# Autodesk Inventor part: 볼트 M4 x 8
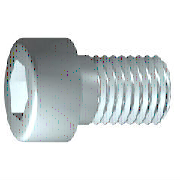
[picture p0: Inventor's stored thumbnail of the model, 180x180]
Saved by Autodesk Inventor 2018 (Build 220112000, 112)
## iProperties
IsCustomPart: 1
Created: 2012-02
Part Number: 볼트 M4 x 8
Material: 스테인리스강
Description: 6각 소켓 머리 캡 나사
Document SubType Name: Modeling
Standard: ISO 4762
Designer: mduedu
Standard Revision: Fourth edition 2004-03-01
Standards Organization: ISO
Language: ko-KR
Size Designation: M4 x 8
Categories: <MemberInstance><Categories><Category DisplayName="조임쇠" InternalName="e4da775c-781d-43d5-af7c-5136215cf5a6" Mnemonic="FSTN"><Category DisplayName="볼트" InternalN
Density: 7.75 g/cm^3
Appearance: 반광택
Author: mduedu
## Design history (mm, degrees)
sketch "스케치1"
  geometry: L1 (-1, 0)-(8, 0); L2 (8, 0)-(8, 2); L3 (8, 2)-(1.75, 2); L4 (1.75, 2)-(1.32, 2); L5 (1.32, 2)-(0, 2); L6 (0, 2)-(0, 3.5); L7 (0, 3.5)-(-4, 3.5); L8 (-4, 3.5)-(-4, 1.732); L9 (-4, 1.732)-(-2, 1.732); L10 (-2, 1.732)-(-1, 0); L11 (-6.4, 0)-(10.4, 0) reference; L12 (0, -0.7)-(0, 4.2) reference; L13 (1.75, 2)-(0, 2)
  constraints: 22 end point, 6 parallel, 2 collinear, 2 perpendicular, 1 horizontal, 1 point on line
  dimensions: "d1" = 6.25 distance from line of L3.end L2 (= GEL); "d2" = 0.42952 distance of L4.end L3.end (computed from GAL); "d3" = 4 distance between parallel lines of L8 L6 (= KOH); "d4" = 2 distance of L8.end L9.end (= INTI); "d5" = 60 deg angle of L10 L1; "d6" = 4 diameter of L3 L1 (= GD); "d7" = 4 diameter of L5 L1 (= BDM); "d8" = 3.4641 diameter of L9 L1 (= 1.1547 x SW); "d9" = 7 diameter of L7 L1 (= KOD); "d26" = 8 distance between parallel lines of L12 L2 (= NLG)
revolve "본체" sketch "스케치1" stored, may be unused: angle "d10" = 90 deg
sketch "스케치2"
  geometry: L1 (0, -4.9)-(0, 4.9) reference; L2 (-4.9, 0)-(4.9, 0) reference; L3 (1.732, 0)-(0.866, -1.5); L4 (0.866, -1.5)-(-0.866, -1.5); L5 (-0.866, -1.5)-(-1.732, 0); L6 (-1.732, 0)-(-0.866, 1.5); L7 (-0.866, 1.5)-(0.866, 1.5); L8 (0.866, 1.5)-(1.732, 0); 2 further points
  constraints: 12 end point, 1 coincident, 1 horizontal alignment, 1 point on line, 12 other
extrude "슬롯" join sketch "스케치2" stored distance "d11" = 10; taper "d12" = 0 deg
workplane "Work Plane1"
fillet "Fillet2" dims "d30" = 0.1 (= R)
body "Solid1"
fillet "모깎기1" dims "d17" = 0.4 (= RR)
feature "스레드" dims "d13" = 6.25 (= GEL), "d14" = 0
chamfer "모따기1" distance "d15" = 0.42941 (= -0.5 x SPD + 0.5 x GD); stored, may be unused: second distance "d16" = 0.42941 (= GUL), angle "d27" = 45 deg
other parameters: "GD" = 4 [user parameter; used in 2 equation terms], "NLG" = 8 [user parameter; used in 1 equation term], "GEL" = 6.25 [user parameter; used in 2 equation terms], "KOD" = 7 [user parameter; used in 1 equation term], "KOH" = 4 [user parameter; used in 1 equation term], "INTI" = 2 [user parameter; used in 1 equation term], "GAL" = 0.42941 (= 0.61345 x PTC) [user parameter; used in 1 equation term], "GUL" = 0.42941 (= 0.61345 x PTC) [user parameter; used in 1 equation term], "BDM" = 4 (= NND) [user parameter; used in 1 equation term], "SW" = 3 [user parameter; used in 2 equation terms], "RR" = 0.4 [user parameter; used in 1 equation term], "SPD" = 3.14117 (= NND - 1.2269 x PTC) [user parameter; used in 1 equation term], "d19" = 0, "d28" = 0, "d29" = 0, "R" = 0.1 [user parameter; used in 1 equation term], "TOA" = 30 deg [user parameter], "GD1" = 3.14117 (= THREADDIA - 1.2269 x PTC) [user parameter], "THREADDIA" = 4 [user parameter; used in 1 equation term], "FAWI" = 45 deg [user parameter], "TPU" = 14.28571 (computed from PTC) [user parameter], "PTC" = 0.7 [user parameter; used in 5 equation terms], "NND" = 4 [user parameter; used in 2 equation terms], "E0" = 3.465 (= 1.155 x SW) [user parameter]
